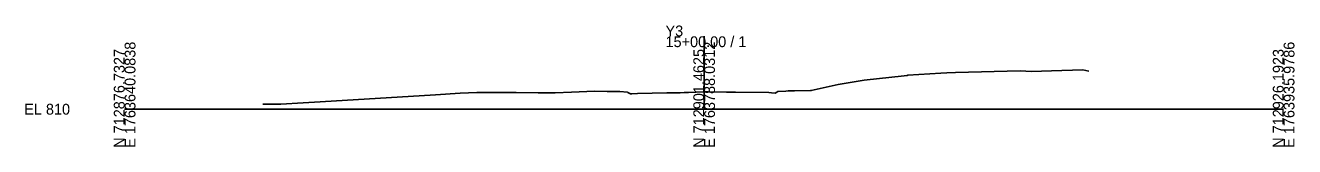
# Model space of a CAD drawing. Extents: x -26 to 2903, y -10 to 5022.
# Drawn here: x -25.7 to 302.8, y 4990.3 to 5021.7 of the extents above; entities that cross this region are included whole.
import ezdxf

# ---------------------------------------------------------------- set-up
doc = ezdxf.new("R2010")
doc.units = 0
for name, color, linetype in [('Default', 7, 'Continuous'), ('Exist Cross Section Cell', 7, 'Continuous'), ('Exist XS Ground Line', 7, 'Continuous')]:
    doc.layers.add(name, color=color, linetype=linetype)

msp = doc.modelspace()

# ---------------------------------------------------------------- linework, layer by layer
at = {"layer": 'Exist Cross Section Cell'}
for p, q in [((150, 5000), (150, 5018.88)), ((0, 5000), (150, 5000)), ((150, 5000), (300, 5000))]:
    msp.add_line(p, q, dxfattribs=at)
at = {"layer": 'Exist XS Ground Line'}
msp.add_lwpolyline([(35.74, 5001.34), (36.62, 5001.32), (37.84, 5001.29), (39.64, 5001.29), (40.47, 5001.31), (46.2, 5001.69), (50.61, 5001.92), (80.47, 5003.73), (86.88, 5004.15), (91.16, 5004.36), (98.32, 5004.35), (101.3, 5004.3), (107.01, 5004.25), (111.44, 5004.21), (115.69, 5004.43), (121.58, 5004.67), (124.93, 5004.56), (128.15, 5004.6), (130.12, 5004.43), (130.27, 5004.34), (130.91, 5003.98), (131.28, 5004), (132.77, 5004.1), (140.34, 5004.23), (142.26, 5004.26), (143.81, 5004.28), (144.82, 5004.32), (145.99, 5004.36), (149.92, 5004.52), (150, 5004.52), (150.93, 5004.5), (155.76, 5004.45), (158.13, 5004.43), (166.72, 5004.35), (167.4, 5004.26), (168.39, 5004.12), (168.82, 5004.39), (169.09, 5004.58), (171.15, 5004.67), (171.72, 5004.76), (173.41, 5004.78), (177.53, 5004.86), (177.72, 5004.82), (180.79, 5005.53), (184.73, 5006.39), (191.43, 5007.49), (201.78, 5008.68), (202.56, 5008.77), (202.69, 5008.79), (211.25, 5009.33), (212.83, 5009.42), (215.05, 5009.53), (231.78, 5009.92), (234.76, 5009.78), (239.93, 5009.96), (248.05, 5010.16), (249.55, 5009.82)], dxfattribs=at)

# ---------------------------------------------------------------- texts
at = {"layer": 'Default'}
msp.add_text('-', height=0.0001, dxfattribs=at).set_placement((0, 5000))
at = {"layer": 'Exist Cross Section Cell'}
for s, p in [('Y3', (140, 5018.88)), ('15+00.00 / 1', (140, 5016.08)), ('EL 810', (-26, 4998.6))]:
    msp.add_text(s, height=2.8, dxfattribs=at).set_placement(p)
for s, p in [('E 1763640.0838', (2.8, 4990)), ('E 1763788.0312', (152.8, 4990)), ('E 1763935.9786', (302.8, 4990)), ('N 712876.7327', (0, 4990)), ('N 712901.4625', (150, 4990)), ('N 712926.1923', (300, 4990))]:
    msp.add_text(s, height=2.8, rotation=90, dxfattribs=at).set_placement(p)

doc.saveas('drawing.dxf')
